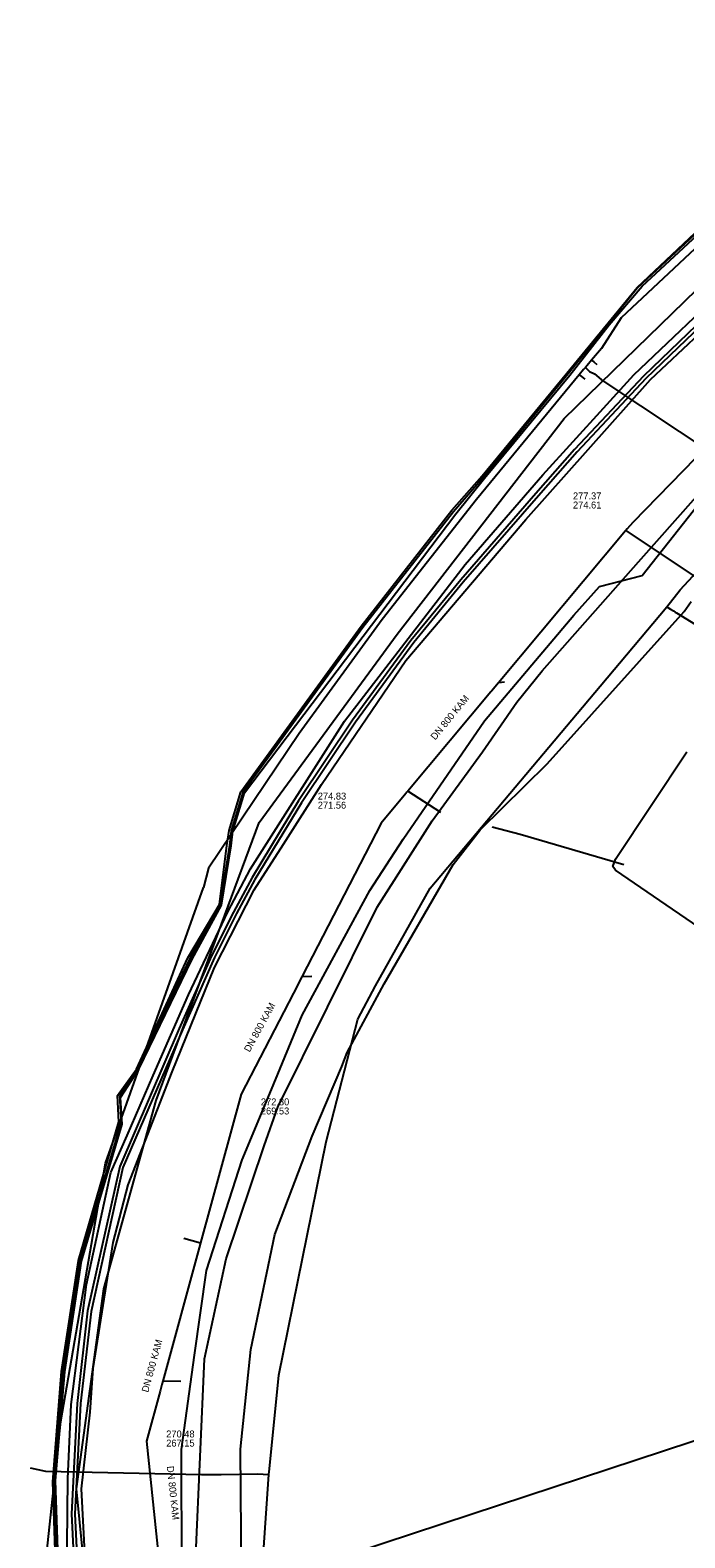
# Model space of a CAD drawing. Extents: x -598233 to -596890, y -1157848 to -1156431.
# Drawn here: x -597177.2 to -597101.7, y -1157171.2 to -1156997.4 of the extents above; entities that cross this region are included whole.
import ezdxf

# ---------------------------------------------------------------- set-up
doc = ezdxf.new("R2010")
doc.units = 0
for name, color, linetype in [('Vrstva 1', 7, 'Continuous'), ('Vrstva 12', 7, 'Continuous'), ('Vrstva 13', 7, 'Continuous'), ('Vrstva 19', 7, 'Continuous'), ('Vrstva 44', 7, 'Continuous'), ('Vrstva 55', 7, 'Continuous'), ('Vrstva 58', 7, 'Continuous'), ('Vrstva 9', 7, 'Continuous')]:
    doc.layers.add(name, color=color, linetype=linetype)

msp = doc.modelspace()

# ---------------------------------------------------------------- linework, layer by layer
at = {"layer": 'Vrstva 1'}
msp.add_line((-597096.38, -1157063.2), (-597108.55, -1157055.07), dxfattribs=at)
msp.add_lwpolyline([(-597108.74, -1157093.63), (-597120.69, -1157090.12), (-597123.93, -1157089.29)], dxfattribs=at)
at = {"layer": 'Vrstva 12'}
for points in [[(-597150.21, -1157126), (-597148.63, -1157121.55), (-597137.17, -1157098.5), (-597130.84, -1157088.57), (-597125.05, -1157080.61), (-597121.1, -1157074.87), (-597118.16, -1157071.29), (-597107.05, -1157058.71), (-597100.43, -1157051.22), (-597096.15, -1157046.37)], [(-597157.49, -1157179.51), (-597158.1, -1157173.16), (-597157.09, -1157150.55), (-597154.58, -1157139.04), (-597150.21, -1157126)]]:
    msp.add_lwpolyline(points, dxfattribs=at)
at = {"layer": 'Vrstva 13'}
for p, q in [((-597113.89, -1157037.16), (-597113.64, -1157037.37)), ((-597113.64, -1157037.37), (-597113.27, -1157037.67)), ((-597113.19, -1157036.33), (-597113.4, -1157036.57)), ((-597112.98, -1157036.09), (-597113.19, -1157036.33)), ((-597113.19, -1157036.33), (-597112.96, -1157036.56)), ((-597046, -1157081.19), (-597111.36, -1157037.72))]:
    msp.add_line(p, q, dxfattribs=at)
for points in [[(-596967.78, -1156864.53), (-596968.28, -1156866.45), (-596969.12, -1156869.63), (-596975.82, -1156881.68), (-596987.36, -1156902), (-596995.97, -1156916.01), (-597005.76, -1156929.74), (-597017.4, -1156942.73), (-597033.49, -1156958.74), (-597059.77, -1156983.91), (-597076.36, -1156999.81), (-597090.23, -1157012.97), (-597109.08, -1157030.59), (-597111.35, -1157034.13), (-597112.48, -1157035.47), (-597112.98, -1157036.09)], [(-597112.48, -1157035.47), (-597112.23, -1157035.67), (-597111.86, -1157035.97)], [(-597113.4, -1157036.57), (-597113.89, -1157037.16), (-597125.75, -1157051.54), (-597136.6, -1157065.38), (-597146.18, -1157078.5), (-597156.61, -1157094.01), (-597157.21, -1157096.24)], [(-597112.96, -1157036.56), (-597112.73, -1157036.79), (-597112.12, -1157037.06), (-597111.36, -1157037.72)], [(-597175.11, -1157174.55), (-597175.28, -1157173.18), (-597173.64, -1157157.78), (-597168.49, -1157128.01), (-597157.21, -1157096.24)]]:
    msp.add_lwpolyline(points, dxfattribs=at)
at = {"layer": 'Vrstva 19'}
for points in [[(-597111.47, -1157073.04), (-597103.79, -1157063.92), (-597102.25, -1157061.93), (-597076.16, -1157033.78)], [(-597103.79, -1157063.92), (-597103.39, -1157064.17), (-597103.05, -1157064.38), (-597102.85, -1157064.5), (-597102.7, -1157064.59), (-597068.31, -1157085.72), (-597062.86, -1157088.77), (-597055.73, -1157092.94)], [(-597131.23, -1157256.42), (-597131.33, -1157256.2), (-597131.98, -1157254.59), (-597134.85, -1157247.55), (-597135.72, -1157245.03), (-597136.1, -1157243.94), (-597143.85, -1157221.61), (-597148.02, -1157203.36), (-597150.84, -1157180.66), (-597149.66, -1157163.89), (-597149.61, -1157163.22), (-597148.51, -1157152.46), (-597143.08, -1157125.54), (-597139.43, -1157111.4), (-597137.36, -1157107.57), (-597131.08, -1157096.32), (-597111.47, -1157073.04)], [(-597177.18, -1157163.12), (-597175.42, -1157163.5), (-597157.43, -1157163.89), (-597157.07, -1157163.9), (-597155.17, -1157163.88)], [(-597155.17, -1157163.88), (-597150.98, -1157163.83), (-597149.66, -1157163.89)]]:
    msp.add_lwpolyline(points, dxfattribs=at)
at = {"layer": 'Vrstva 44'}
for points in [[(-597172.47, -1157155.84), (-597170.67, -1157141.98), (-597167.89, -1157129.08), (-597165.98, -1157124.83), (-597163.02, -1157117.92), (-597158.94, -1157108.63), (-597154.41, -1157099.06), (-597151.77, -1157094.09), (-597140.96, -1157077.07), (-597127.03, -1157059.02), (-597118.11, -1157048.7), (-597107.6, -1157037.16), (-597096.04, -1157026.19), (-597085.38, -1157015.65), (-597074.66, -1157004.75), (-597063.06, -1156993.3)], [(-597174.11, -1157178.24), (-597174.58, -1157164.73), (-597173.56, -1157152.03), (-597171.6, -1157139.24), (-597166.95, -1157123.25), (-597167.1, -1157120.2), (-597164.93, -1157117.17), (-597159.01, -1157104.35), (-597155.37, -1157098.19), (-597154.5, -1157091.4), (-597154.25, -1157089.68), (-597152.88, -1157085.23), (-597139.02, -1157066.13), (-597128.59, -1157052.77), (-597125.1, -1157048.82), (-597115.33, -1157036.96), (-597107.24, -1157027.09), (-597094.52, -1157015.13)], [(-597094.54, -1157015.38), (-597107.17, -1157027.15), (-597115.18, -1157037.06), (-597124.96, -1157048.98), (-597128.4, -1157052.96), (-597138.85, -1157066.27), (-597152.68, -1157085.3), (-597154.03, -1157089.71), (-597154.22, -1157091.38), (-597155.29, -1157098.21), (-597158.73, -1157104.36), (-597164.87, -1157117.19), (-597166.9, -1157120.26), (-597166.68, -1157123.3), (-597171.45, -1157139.26), (-597173.41, -1157152.05), (-597174.45, -1157164.54), (-597173.97, -1157178.22)], [(-597173.81, -1157178.2), (-597174.24, -1157164.57), (-597173.19, -1157152.06), (-597171.26, -1157139.31), (-597166.59, -1157123.51), (-597166.78, -1157120.44), (-597164.64, -1157117.18), (-597158.49, -1157104.52), (-597155.14, -1157098.29), (-597154.03, -1157091.46), (-597153.84, -1157089.74), (-597152.48, -1157085.35), (-597128.13, -1157053.18), (-597124.81, -1157049.08), (-597115, -1157037.19), (-597110.45, -1157031.39), (-597106.65, -1157026.96), (-597094.45, -1157015.65)], [(-597097.34, -1157028.51), (-597106.49, -1157037.31), (-597114.43, -1157045.77), (-597118.89, -1157050.86), (-597127.56, -1157060.78), (-597133.29, -1157067.77), (-597140.03, -1157076.95), (-597146.25, -1157086.26), (-597151.61, -1157095.11), (-597153.75, -1157099.07), (-597156.29, -1157104.13), (-597160, -1157112.5), (-597166.86, -1157128.39), (-597170.56, -1157145.03), (-597171.76, -1157155.69), (-597172.43, -1157168.41), (-597171.46, -1157187.97), (-597170.62, -1157194.72), (-597170.05, -1157199.78), (-597169.47, -1157203.12), (-597169.57, -1157203.58), (-597169.7, -1157204), (-597169.79, -1157204.29)], [(-597097.06, -1157028.8), (-597106.21, -1157037.59), (-597114.13, -1157046.04), (-597118.59, -1157051.12), (-597127.26, -1157061.04), (-597132.97, -1157068.02), (-597139.7, -1157077.18), (-597145.91, -1157086.47), (-597151.27, -1157095.31), (-597153.4, -1157099.25), (-597155.93, -1157104.3), (-597159.63, -1157112.66), (-597166.48, -1157128.51), (-597170.16, -1157145.09), (-597171.36, -1157155.72), (-597172.03, -1157168.41), (-597171.06, -1157187.94), (-597170.22, -1157194.68), (-597169.65, -1157199.72), (-597168.44, -1157205.45), (-597168.68, -1157206.23), (-597168.75, -1157206.69), (-597168.78, -1157206.89)], [(-597172.94, -1157175.78), (-597172.83, -1157164.37), (-597172.47, -1157155.84)]]:
    msp.add_lwpolyline(points, dxfattribs=at)
at = {"layer": 'Vrstva 55'}
for points in [[(-597170.85, -1157173.64), (-597171.28, -1157165.54), (-597170.27, -1157156.7), (-597169.91, -1157151.69), (-597167.63, -1157137.17), (-597165.89, -1157130.51), (-597160.8, -1157117.5), (-597155.93, -1157105.48), (-597151.35, -1157096.51), (-597148, -1157091.24), (-597143.59, -1157084.36), (-597133.87, -1157070.07), (-597120.07, -1157053.82), (-597105.69, -1157037.7), (-597096.28, -1157028.86)], [(-597159.68, -1157175.05), (-597159.74, -1157160.99), (-597158.25, -1157150.14), (-597156.87, -1157140.38), (-597152.74, -1157127.62), (-597149.36, -1157119.52), (-597145.82, -1157110.96), (-597138.04, -1157096.58), (-597134.19, -1157090.66), (-597124.82, -1157077.04), (-597114.52, -1157064.88), (-597111.56, -1157061.56), (-597106.65, -1157060.28), (-597097.1, -1157048.22)], [(-597094.76, -1157104.48), (-597104.62, -1157097.73), (-597109.72, -1157094.25), (-597110.02, -1157093.84), (-597109.71, -1157092.99), (-597101.48, -1157080.63)]]:
    msp.add_lwpolyline(points, dxfattribs=at)
at = {"layer": 'Vrstva 58'}
for points in [[(-596922.36, -1157613.63), (-596952.88, -1157577.73), (-597153.35, -1157366.73), (-597150.38, -1157360.9), (-597143.15, -1157348.79), (-597141.76, -1157340.35), (-597141.76, -1157332.41), (-597142.33, -1157328.4), (-597136.65, -1157325.05), (-597127.33, -1157309.4), (-597155.19, -1157243.69), (-597168.69, -1157197.35), (-597171.83, -1157165.56), (-597168.69, -1157142.5), (-597162.65, -1157120.78), (-597150.78, -1157088.76), (-597134.89, -1157067.04), (-597115.64, -1157042.19), (-597035.06, -1156963.83)], [(-597152.79, -1157180.39), (-597152.94, -1157160.98), (-597151.76, -1157149.49), (-597148.98, -1157136.24), (-597144.68, -1157124.91), (-597141.25, -1157116.86), (-597140.65, -1157115.26), (-597136.37, -1157107.35), (-597128.43, -1157093.61), (-597125.33, -1157089.59), (-597117.58, -1157082), (-597101.81, -1157064.45), (-597100.99, -1157063.27)]]:
    msp.add_lwpolyline(points, dxfattribs=at)
at = {"layer": 'Vrstva 9'}
for p, q in [((-597122.53, -1157072.59), (-597123.21, -1157072.67)), ((-597129.84, -1157087.6), (-597133.65, -1157085.16)), ((-597144.72, -1157106.5), (-597145.87, -1157106.53)), ((-597159.46, -1157136.66), (-597157.53, -1157137.18)), ((-597159.8, -1157153.17), (-597161.89, -1157153.13)), ((-597093.03, -1157157.52), (-597126.37, -1157168.5)), ((-597163.78, -1157160.06), (-597161.45, -1157182.19)), ((-597126.37, -1157168.5), (-597156.73, -1157178.49))]:
    msp.add_line(p, q, dxfattribs=at)
for points in [[(-597076.74, -1157022.48), (-597095.12, -1157041.26), (-597095.2, -1157041.35), (-597095.62, -1157041.78), (-597095.81, -1157041.97), (-597095.99, -1157042.16), (-597096.14, -1157042.31), (-597107.74, -1157054.17)], [(-597107.74, -1157054.17), (-597108.38, -1157054.93), (-597108.57, -1157055.16), (-597123.21, -1157072.67), (-597124.01, -1157073.63), (-597124.08, -1157073.71), (-597133.65, -1157085.16), (-597133.75, -1157085.27), (-597133.88, -1157085.43), (-597136.72, -1157088.82)], [(-597136.72, -1157088.82), (-597145.87, -1157106.53), (-597146.21, -1157107.2), (-597146.3, -1157107.37), (-597152.85, -1157120.05)], [(-597152.85, -1157120.05), (-597157.53, -1157137.18), (-597157.69, -1157137.77), (-597161.89, -1157153.13), (-597161.99, -1157153.53), (-597162.2, -1157154.27), (-597163.78, -1157160.06)]]:
    msp.add_lwpolyline(points, dxfattribs=at)

# ---------------------------------------------------------------- texts
at = {"layer": 'Vrstva 12'}
for s, p in [('277.37', (-597114.62, -1157051.52)), ('274.61', (-597114.62, -1157052.57)), ('274.83', (-597144.03, -1157086.11)), ('271.56', (-597144.03, -1157087.16)), ('272.80', (-597150.59, -1157121.35)), ('269.53', (-597150.59, -1157122.4)), ('270.48', (-597161.5, -1157159.62)), ('267.15', (-597161.5, -1157160.67))]:
    msp.add_text(s, height=0.8, dxfattribs=at).set_placement(p)
for rotation, p in [(50.5922, (-597130.49, -1157079.31)), (61.3638, (-597151.88, -1157115.28)), (74.7137, (-597163.58, -1157154.48)), (275.9938, (-597161.43, -1157162.95))]:
    msp.add_text('DN 800 KAM', height=0.8, rotation=rotation, dxfattribs=at).set_placement(p)

doc.saveas('drawing.dxf')
